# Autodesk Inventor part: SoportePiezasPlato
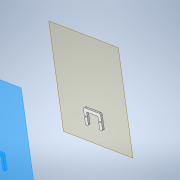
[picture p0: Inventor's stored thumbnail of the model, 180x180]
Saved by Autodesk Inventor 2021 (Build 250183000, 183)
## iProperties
Created: 2021-03
Part Number: SoportePiezasPlato
Material: Genérico
Document SubType Name: Modeling
Designer: ATOUZA
Density: 1 g/cm^3
Appearance: Valor por defecto
Author: ATOUZA
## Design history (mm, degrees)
node "Plano de trabajo3"
sketch "Boceto1"
  geometry: L1 (-17.5, -60.3)-(-17.5, -95.3) reference; L2 (17.5, -60.3)-(-17.5, -60.3) reference; L3 (17.5, -95.3)-(17.5, -60.3) reference; L4 (17.5, -95.3)-(-17.5, -95.3); L5 (-17.5, -95.3)-(-17.5, -60.3); L6 (-17.5, -60.3)-(17.5, -60.3); L7 (17.5, -60.3)-(17.5, -95.3); L8 (17.5, -95.3)-(-17.5, -60.3); L9 (-17.5, -95.3)-(17.5, -60.3); L10 (-18, -91.3)-(-18, -59.8); L11 (-18, -59.8)-(18, -59.8); L12 (18, -59.8)-(18, -91.3); L13 (-27, -91.3)-(-27, -54.8); L14 (-23, -50.8)-(23, -50.8); L15 (27, -54.8)-(27, -91.3); L16 (22, -95.3)-(23, -95.3); L17 (-23, -95.3)-(-22, -95.3); L18 (-22.5, -95.3)-(-22.5, -50.8); L19 (22.5, -95.3)-(22.5, -50.8); C1 r 2 at (-22.5, -73.05); C2 r 2 at (22.5, -73.05); A1 r 4 centre (-23, -54.8) between (-23, -50.8) and (-27, -54.8); A2 r 4 centre (23, -54.8) between (27, -54.8) and (23, -50.8); A3 r 4 centre (23, -91.3) between (23, -95.3) and (27, -91.3); A4 r 4 centre (22, -91.3) between (18, -91.3) and (22, -95.3); A5 r 4 centre (-22, -91.3) between (-22, -95.3) and (-18, -91.3); A6 r 4 centre (-23, -91.3) between (-27, -91.3) and (-23, -95.3); 2 further points
  constraints: 32 end point, 12 point on circle, 12 tangent, 8 centre point, 6 midpoint, 5 equal radius, 4 perpendicular, 2 horizontal, 2 parallel, 2 point on line, 4 other
  dimensions: "d0" = 0.5 distance between parallel lines of L2 L11; "d1" = 9 distance between parallel lines of L10 L13; "d2" = 36 distance of L10.end L11.end (derived); "d3" = 4 diameter of C1; "d4" = 4 diameter of C2; "d5" = 4 radius of A1 (derived)
extrude "Extrusión1" new body sketch "Boceto1" distance "d6" = 5.5; taper "d7" = 0 deg
node "Sólido1"
